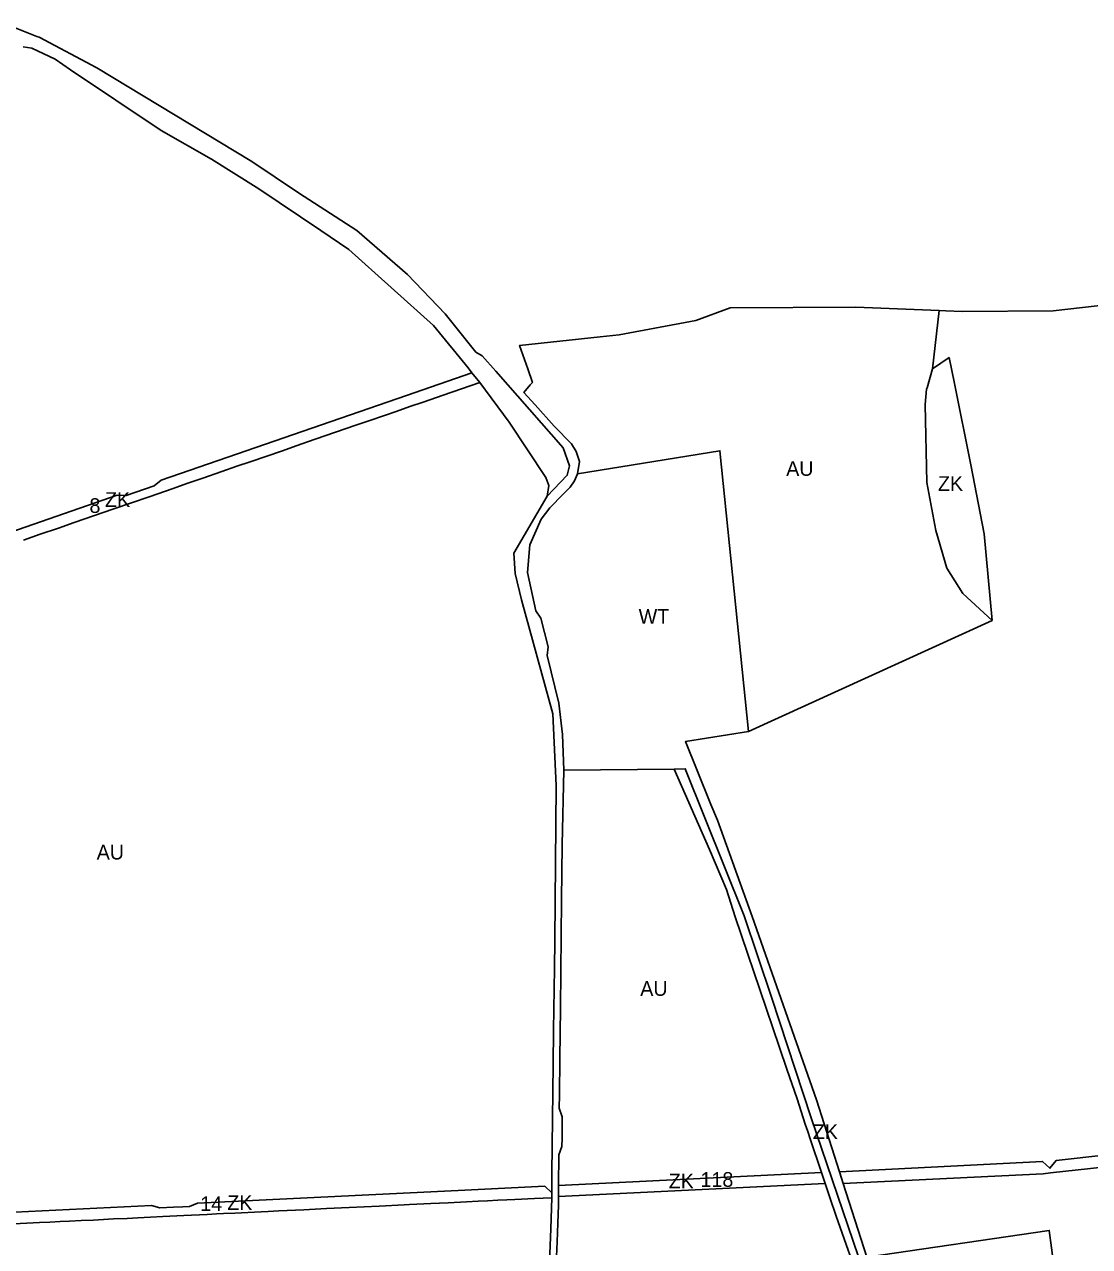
# Model space of a CAD drawing. Extents: x -521939 to -516426, y -1197857 to -1189551.
# Drawn here: x -520047 to -519323, y -1190643 to -1189811 of the extents above; entities that cross this region are included whole.
import ezdxf

# ---------------------------------------------------------------- set-up
doc = ezdxf.new("R2010")
doc.units = 0
for name, color, linetype in [('90640013', 7, 'Continuous'), ('90710013', 7, 'Continuous'), ('90710023', 7, 'Continuous'), ('90750013', 7, 'Continuous'), ('ID_navrh', 7, 'Continuous')]:
    doc.layers.add(name, color=color, linetype=linetype)

msp = doc.modelspace()

# ---------------------------------------------------------------- linework, layer by layer
at = {"layer": '90640013'}
msp.add_lwpolyline([(-519474.2, -1190649.71), (-519490.33, -1190599.63), (-519492.88, -1190591.75), (-519508.5, -1190542.63), (-519552.15, -1190418.05), (-519575.87, -1190352.44), (-519580.3, -1190341.74), (-519589.71, -1190318.55), (-519597.55, -1190298.89), (-519554.65, -1190292.08), (-519574.25, -1190101.1), (-519671.12, -1190116.75), (-519673.07, -1190121.57), (-519676.05, -1190125.81), (-519680.93, -1190130.62), (-519690, -1190140), (-519695.89, -1190147.52), (-519703.56, -1190164.98), (-519705.08, -1190183.98), (-519699.51, -1190210.06), (-519696.18, -1190214.95), (-519691.12, -1190234.48), (-519691.66, -1190240.37), (-519683.84, -1190272.83), (-519681.25, -1190294.06), (-519680.51, -1190318.33), (-519605.33, -1190317.74), (-519597.8, -1190317.46), (-519557.64, -1190417.47), (-519539.16, -1190472.93), (-519512.13, -1190554.9), (-519465.6, -1190691.56)], dxfattribs=at)
at = {"layer": '90710013'}
for points in [[(-520048.37, -1189826.26), (-520042.45, -1189827.13), (-520026.64, -1189834.56), (-520016.21, -1189841.8), (-519954.44, -1189883.11), (-519920.2, -1189902.73), (-519887.92, -1189922.82), (-519845.8, -1189951.09), (-519826.71, -1189964.04), (-519769.14, -1190015.86), (-519745.61, -1190044.71), (-519742.92, -1190048.01), (-519737.67, -1190054.66), (-519717.63, -1190081.69), (-519692.57, -1190119.33), (-519690.61, -1190124.71), (-519691.71, -1190131.91), (-519678.13, -1190117.74), (-519676.51, -1190111.34), (-519680.84, -1190099.12), (-519726.6, -1190046.96), (-519736.08, -1190036.41), (-519740.21, -1190033.91), (-519761.19, -1190007.99), (-519786.78, -1189981.15), (-519821.23, -1189951.29), (-519861, -1189925.67), (-519892.81, -1189904.25), (-519998.21, -1189840.6), (-520037.43, -1189819.73), (-520038.96, -1189819.12), (-520059.38, -1189810.98)], [(-519429.52, -1190045.26), (-519433.28, -1190058.31), (-519433.52, -1190059.13), (-519434.55, -1190069.58), (-519433.46, -1190122.75), (-519427.39, -1190155.37), (-519419.73, -1190181.02), (-519408.88, -1190198.29), (-519388.96, -1190216.56), (-519394.35, -1190157.59), (-519403.44, -1190110.7), (-519414.58, -1190055.36), (-519418.22, -1190037.69), (-519429.52, -1190045.26)], [(-519465.6, -1190691.56), (-519512.13, -1190554.9), (-519539.16, -1190472.93), (-519557.64, -1190417.47), (-519597.8, -1190317.46), (-519605.33, -1190317.74), (-519581.21, -1190372.49), (-519569.8, -1190399.55), (-519563.85, -1190418.24), (-519538.35, -1190493.03), (-519528.57, -1190521.96), (-519521.72, -1190542.14), (-519516.17, -1190559.23), (-519514.47, -1190564.36), (-519512.9, -1190569.2), (-519505.17, -1190592.27), (-519502.67, -1190599.7), (-519499.5, -1190609.21), (-519495.04, -1190621.79), (-519491.09, -1190633.4), (-519481.62, -1190659.8)]]:
    msp.add_lwpolyline(points, dxfattribs=at)
at = {"layer": '90710023'}
for points in [[(-519742.92, -1190048.01), (-519787.45, -1190063.39), (-519954.51, -1190121.09), (-519959.21, -1190124.83), (-519978.27, -1190131.41), (-519984.27, -1190131.37), (-520061.95, -1190158.2)], [(-520048.21, -1190161.91), (-520036.77, -1190157.93), (-520024.36, -1190153.64), (-520013.6, -1190149.97), (-519986.68, -1190140.64), (-519962.62, -1190132.36), (-519946.2, -1190126.69), (-519936.96, -1190123.44), (-519926.15, -1190119.68), (-519913.25, -1190115.28), (-519903.02, -1190111.63), (-519893.94, -1190108.6), (-519871.89, -1190101.04), (-519862.6, -1190097.78), (-519849.58, -1190093.29), (-519821.87, -1190083.74), (-519813.04, -1190080.72), (-519802.38, -1190076.99), (-519794.41, -1190074.26), (-519785.22, -1190071.01), (-519776.17, -1190067.93), (-519762.5, -1190063.2), (-519737.67, -1190054.66), (-519742.92, -1190048.01)], [(-519168.97, -1190564.24), (-519345.4, -1190584.01), (-519349.64, -1190589.23), (-519354.59, -1190584.65), (-519492.88, -1190591.75)], [(-519492.88, -1190591.75), (-519490.33, -1190599.63), (-519354.17, -1190593), (-519349.34, -1190592.5), (-519294.71, -1190586.4)], [(-519684.06, -1190601.07), (-519684.13, -1190608.58), (-519502.67, -1190599.7), (-519505.17, -1190592.27), (-519684.06, -1190601.07)], [(-519688.62, -1190605.97), (-519693.24, -1190601.52), (-519752.34, -1190604.4), (-519929.64, -1190613.04), (-519935.19, -1190615.32), (-519939.78, -1190615.54), (-519946.03, -1190615.85), (-519955.34, -1190616.3), (-519961.08, -1190614.58), (-520119.28, -1190622.29)], [(-520059.37, -1190627.38), (-520045.77, -1190626.72), (-520037.2, -1190626.26), (-520030.12, -1190625.96), (-520023.13, -1190625.6), (-520016.69, -1190625.32), (-520008.95, -1190624.91), (-520000.46, -1190624.51), (-519986.76, -1190623.81), (-519977.56, -1190623.39), (-519970.21, -1190623.03), (-519961.73, -1190622.55), (-519953.25, -1190622.2), (-519938.98, -1190621.52), (-519923.22, -1190620.76), (-519916.75, -1190620.41), (-519912.12, -1190620.15), (-519904.19, -1190619.79), (-519886.32, -1190618.93), (-519881.51, -1190618.7), (-519874.3, -1190618.35), (-519857.39, -1190617.5), (-519842, -1190616.75), (-519826.46, -1190615.97), (-519806.02, -1190614.98), (-519789.16, -1190614.2), (-519785.45, -1190613.97), (-519780.36, -1190613.76), (-519770.89, -1190613.31), (-519759.09, -1190612.73), (-519746.72, -1190612.13), (-519738.62, -1190611.73), (-519732.39, -1190611.44), (-519725.37, -1190611.1), (-519719.21, -1190610.77), (-519713.65, -1190610.53), (-519700.36, -1190609.88), (-519688.65, -1190609.3), (-519688.62, -1190605.97)]]:
    msp.add_lwpolyline(points, dxfattribs=at)
at = {"layer": '90750013'}
for points in [[(-520061.95, -1190158.2), (-519984.27, -1190131.37), (-519978.27, -1190131.41), (-519959.21, -1190124.83), (-519954.51, -1190121.09), (-519787.45, -1190063.39), (-519742.92, -1190048.01), (-519745.61, -1190044.71), (-519769.14, -1190015.86), (-519826.71, -1189964.04), (-519845.8, -1189951.09), (-519887.92, -1189922.82), (-519920.2, -1189902.73), (-519954.44, -1189883.11), (-520016.21, -1189841.8), (-520026.64, -1189834.56), (-520042.45, -1189827.13), (-520048.37, -1189826.26)], [(-519429.52, -1190045.26), (-519425.02, -1190005.62), (-519481.8, -1190003.43), (-519567.31, -1190003.84), (-519590.6, -1190012.36), (-519642.78, -1190022.29), (-519655.77, -1190023.65), (-519710.52, -1190029.36), (-519704.94, -1190045.39), (-519701.77, -1190054.51), (-519703.4, -1190056.13), (-519707.58, -1190061.41), (-519700.01, -1190069.84), (-519686.92, -1190084.42), (-519675.13, -1190096.39), (-519672.04, -1190101.52), (-519669.83, -1190108.42), (-519671.12, -1190116.75), (-519574.25, -1190101.1), (-519554.65, -1190292.08), (-519388.96, -1190216.56), (-519408.88, -1190198.29), (-519419.73, -1190181.02), (-519427.39, -1190155.37), (-519433.46, -1190122.75), (-519434.55, -1190069.58), (-519433.52, -1190059.13), (-519433.28, -1190058.31), (-519429.52, -1190045.26)], [(-519307.47, -1190001.42), (-519347.33, -1190005.8), (-519409.39, -1190006.22), (-519420.4, -1190005.8), (-519425.02, -1190005.62), (-519429.52, -1190045.26), (-519418.22, -1190037.69), (-519414.58, -1190055.36), (-519403.44, -1190110.7), (-519394.35, -1190157.59), (-519388.96, -1190216.56), (-519554.65, -1190292.08), (-519597.55, -1190298.89), (-519589.71, -1190318.55), (-519580.3, -1190341.74), (-519575.87, -1190352.44), (-519552.15, -1190418.05), (-519508.5, -1190542.63), (-519492.88, -1190591.75), (-519354.59, -1190584.65), (-519349.64, -1190589.23), (-519345.4, -1190584.01), (-519168.97, -1190564.24)], [(-520119.28, -1190622.29), (-519961.08, -1190614.58), (-519955.34, -1190616.3), (-519946.03, -1190615.85), (-519939.78, -1190615.54), (-519935.19, -1190615.32), (-519929.64, -1190613.04), (-519752.34, -1190604.4), (-519693.24, -1190601.52), (-519688.62, -1190605.97), (-519688.47, -1190592.56), (-519687.63, -1190518.62), (-519687.37, -1190495.31), (-519686.87, -1190453.12), (-519686.63, -1190434.32), (-519685.58, -1190328.88), (-519687.95, -1190280.17), (-519709.23, -1190202.58), (-519713.62, -1190184.5), (-519714.39, -1190170.65), (-519691.71, -1190131.91), (-519690.61, -1190124.71), (-519692.57, -1190119.33), (-519717.63, -1190081.69), (-519737.67, -1190054.66), (-519762.5, -1190063.2), (-519776.17, -1190067.93), (-519785.22, -1190071.01), (-519794.41, -1190074.26), (-519802.38, -1190076.99), (-519813.04, -1190080.72), (-519821.87, -1190083.74), (-519849.58, -1190093.29), (-519862.6, -1190097.78), (-519871.89, -1190101.04), (-519893.94, -1190108.6), (-519903.02, -1190111.63), (-519913.25, -1190115.28), (-519926.15, -1190119.68), (-519936.96, -1190123.44), (-519946.2, -1190126.69), (-519962.62, -1190132.36), (-519986.68, -1190140.64), (-520013.6, -1190149.97), (-520024.36, -1190153.64), (-520036.77, -1190157.93), (-520048.21, -1190161.91)], [(-519684.06, -1190601.07), (-519505.17, -1190592.27), (-519512.9, -1190569.2), (-519514.47, -1190564.36), (-519516.17, -1190559.23), (-519521.72, -1190542.14), (-519528.57, -1190521.96), (-519538.35, -1190493.03), (-519563.85, -1190418.24), (-519569.8, -1190399.55), (-519581.21, -1190372.49), (-519605.33, -1190317.74), (-519680.51, -1190318.33), (-519681.63, -1190369.22), (-519681.96, -1190406.75), (-519682.78, -1190480.2), (-519683.09, -1190514.75), (-519683.38, -1190539.26), (-519683.51, -1190548.46), (-519681.55, -1190554.22), (-519681.61, -1190558.35), (-519681.63, -1190563.46), (-519681.64, -1190568.72), (-519681.77, -1190574.39), (-519683.86, -1190580.1), (-519684.06, -1190601.07)], [(-519294.71, -1190586.4), (-519349.34, -1190592.5), (-519354.17, -1190593), (-519490.33, -1190599.63), (-519474.2, -1190649.71), (-519350.06, -1190631.54), (-519348.65, -1190643.36), (-519337.21, -1190732.05), (-519333.43, -1190761.83), (-519381.92, -1190770.01), (-519378.78, -1190788), (-519378.08, -1190792.18), (-519376.41, -1190801.97), (-519413.98, -1190808.49), (-519415.74, -1190808.8), (-519420.82, -1190809.69), (-519425.9, -1190810.59)], [(-519435.15, -1190886.72), (-519447.4, -1190798.17), (-519457.49, -1190737.73), (-519465.89, -1190705.97), (-519475.51, -1190677.19), (-519481.62, -1190659.8), (-519491.09, -1190633.4), (-519495.04, -1190621.79), (-519499.5, -1190609.21), (-519502.67, -1190599.7), (-519684.13, -1190608.58), (-519684.13, -1190614.39), (-519684.52, -1190626.67), (-519685, -1190639.32), (-519686.23, -1190669.35), (-519686.8, -1190685.4), (-519687.84, -1190713.61), (-519694.59, -1190887.19), (-519516.08, -1190886.87), (-519435.15, -1190886.72)], [(-519691.85, -1190693.04), (-519689.17, -1190630.58), (-519688.65, -1190609.3), (-519700.36, -1190609.88), (-519713.65, -1190610.53), (-519719.21, -1190610.77), (-519725.37, -1190611.1), (-519732.39, -1190611.44), (-519738.62, -1190611.73), (-519746.72, -1190612.13), (-519759.09, -1190612.73), (-519770.89, -1190613.31), (-519780.36, -1190613.76), (-519785.45, -1190613.97), (-519789.16, -1190614.2), (-519806.02, -1190614.98), (-519826.46, -1190615.97), (-519842, -1190616.75), (-519857.39, -1190617.5), (-519874.3, -1190618.35), (-519881.51, -1190618.7), (-519886.32, -1190618.93), (-519904.19, -1190619.79), (-519912.12, -1190620.15), (-519916.75, -1190620.41), (-519923.22, -1190620.76), (-519938.98, -1190621.52), (-519953.25, -1190622.2), (-519961.73, -1190622.55), (-519970.21, -1190623.03), (-519977.56, -1190623.39), (-519986.76, -1190623.81), (-520000.46, -1190624.51), (-520008.95, -1190624.91), (-520016.69, -1190625.32), (-520023.13, -1190625.6), (-520030.12, -1190625.96), (-520037.2, -1190626.26), (-520045.77, -1190626.72), (-520059.37, -1190627.38)]]:
    msp.add_lwpolyline(points, dxfattribs=at)

# ---------------------------------------------------------------- texts
at = {"layer": '90640013'}
msp.add_text('WT', height=10, rotation=0, dxfattribs=at).set_placement((-519629.48, -1190218.83))
at = {"layer": '90710013'}
for p in [(-519425.86, -1190128.36), (-519510.99, -1190569.45)]:
    msp.add_text('ZK', height=10, rotation=360, dxfattribs=at).set_placement(p)
at = {"layer": '90710023'}
for rotation, p in [(0, (-519992.65, -1190139.25)), (0, (-519609.03, -1190603.01)), (360, (-519909.47, -1190617.69))]:
    msp.add_text('ZK', height=10, rotation=rotation, dxfattribs=at).set_placement(p)
at = {"layer": '90750013'}
for rotation, p in [(0, (-519529.1, -1190118.16)), (0, (-519998.29, -1190379.2)), (360, (-519628.42, -1190471.97))]:
    msp.add_text('AU', height=10, rotation=rotation, dxfattribs=at).set_placement(p)
at = {"layer": 'ID_navrh'}
for s, rotation, p in [('8', 360, (-520003.2, -1190143.38)), ('118', 0, (-519587.4, -1190601.93)), ('14', 0, (-519927.83, -1190618.43))]:
    msp.add_text(s, height=10, rotation=rotation, dxfattribs=at).set_placement(p)

doc.saveas('drawing.dxf')
